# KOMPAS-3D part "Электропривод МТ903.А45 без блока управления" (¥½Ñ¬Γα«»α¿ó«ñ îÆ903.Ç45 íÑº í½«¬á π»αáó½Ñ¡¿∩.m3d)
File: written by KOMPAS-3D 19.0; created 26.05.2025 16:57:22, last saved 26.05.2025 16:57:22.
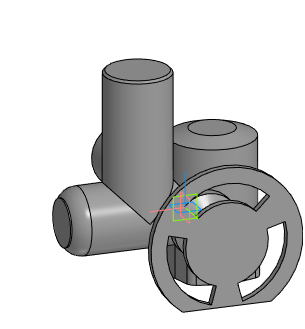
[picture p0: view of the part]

Document properties: Полное имя файла: E:\Dendor Работа Сачек\3D для проекитирвщиков\3.4 Электропривод МТ903.А\stp_Тип МТ903.А без блока управления\Электропривод МТ903.А45 без блока управления.m3d

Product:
- Part/product: Электропривод МТ903.А45 без блока управления

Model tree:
1. Операция без истории:1  (labels: Электропривод МТ903.А45 без блока управления)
